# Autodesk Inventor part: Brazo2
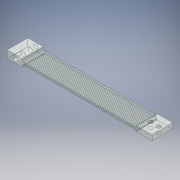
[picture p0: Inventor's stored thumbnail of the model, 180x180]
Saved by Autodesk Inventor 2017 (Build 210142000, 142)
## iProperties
Part Number: Brazo2
Material: Genérico
Document SubType Name: Modeling
Designer: Diego
Density: 1 g/cm^3
Appearance: Valor por defecto
Author: Diego
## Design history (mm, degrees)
derived "Lubina.ipt"
sketch "Boceto1"
  geometry: C1 r 1.95 at (7.25, -3.5) reference; 1 further point
extrude "Extrusión1" new body sketch "Boceto1" distance "d1" = 10; taper "d2" = 0 deg
feature "Combinar1"
feature "Engrosado1" dims "d3" = 0.25, "d4" = 0.25
sketch "Boceto2"
  geometry: C1 r 1.7 at (0, 0) reference; 1 further point
extrude "Extrusión2" join sketch "Boceto2" distance "d5" = 10; taper "d6" = 0 deg
feature "Brazo::Lubina.ipt" dims "d0" = 10
tag "OperaciónIdentificador1"
node "Sólido2"
node "Contorno proyectado1"
node "Sólido1"
